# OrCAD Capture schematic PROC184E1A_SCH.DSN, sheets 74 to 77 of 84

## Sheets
74 78. EVM SOC CURRENT_SENSE_RES: size C; title: SOC Current Sense Resistors; note: PROC184_SCH
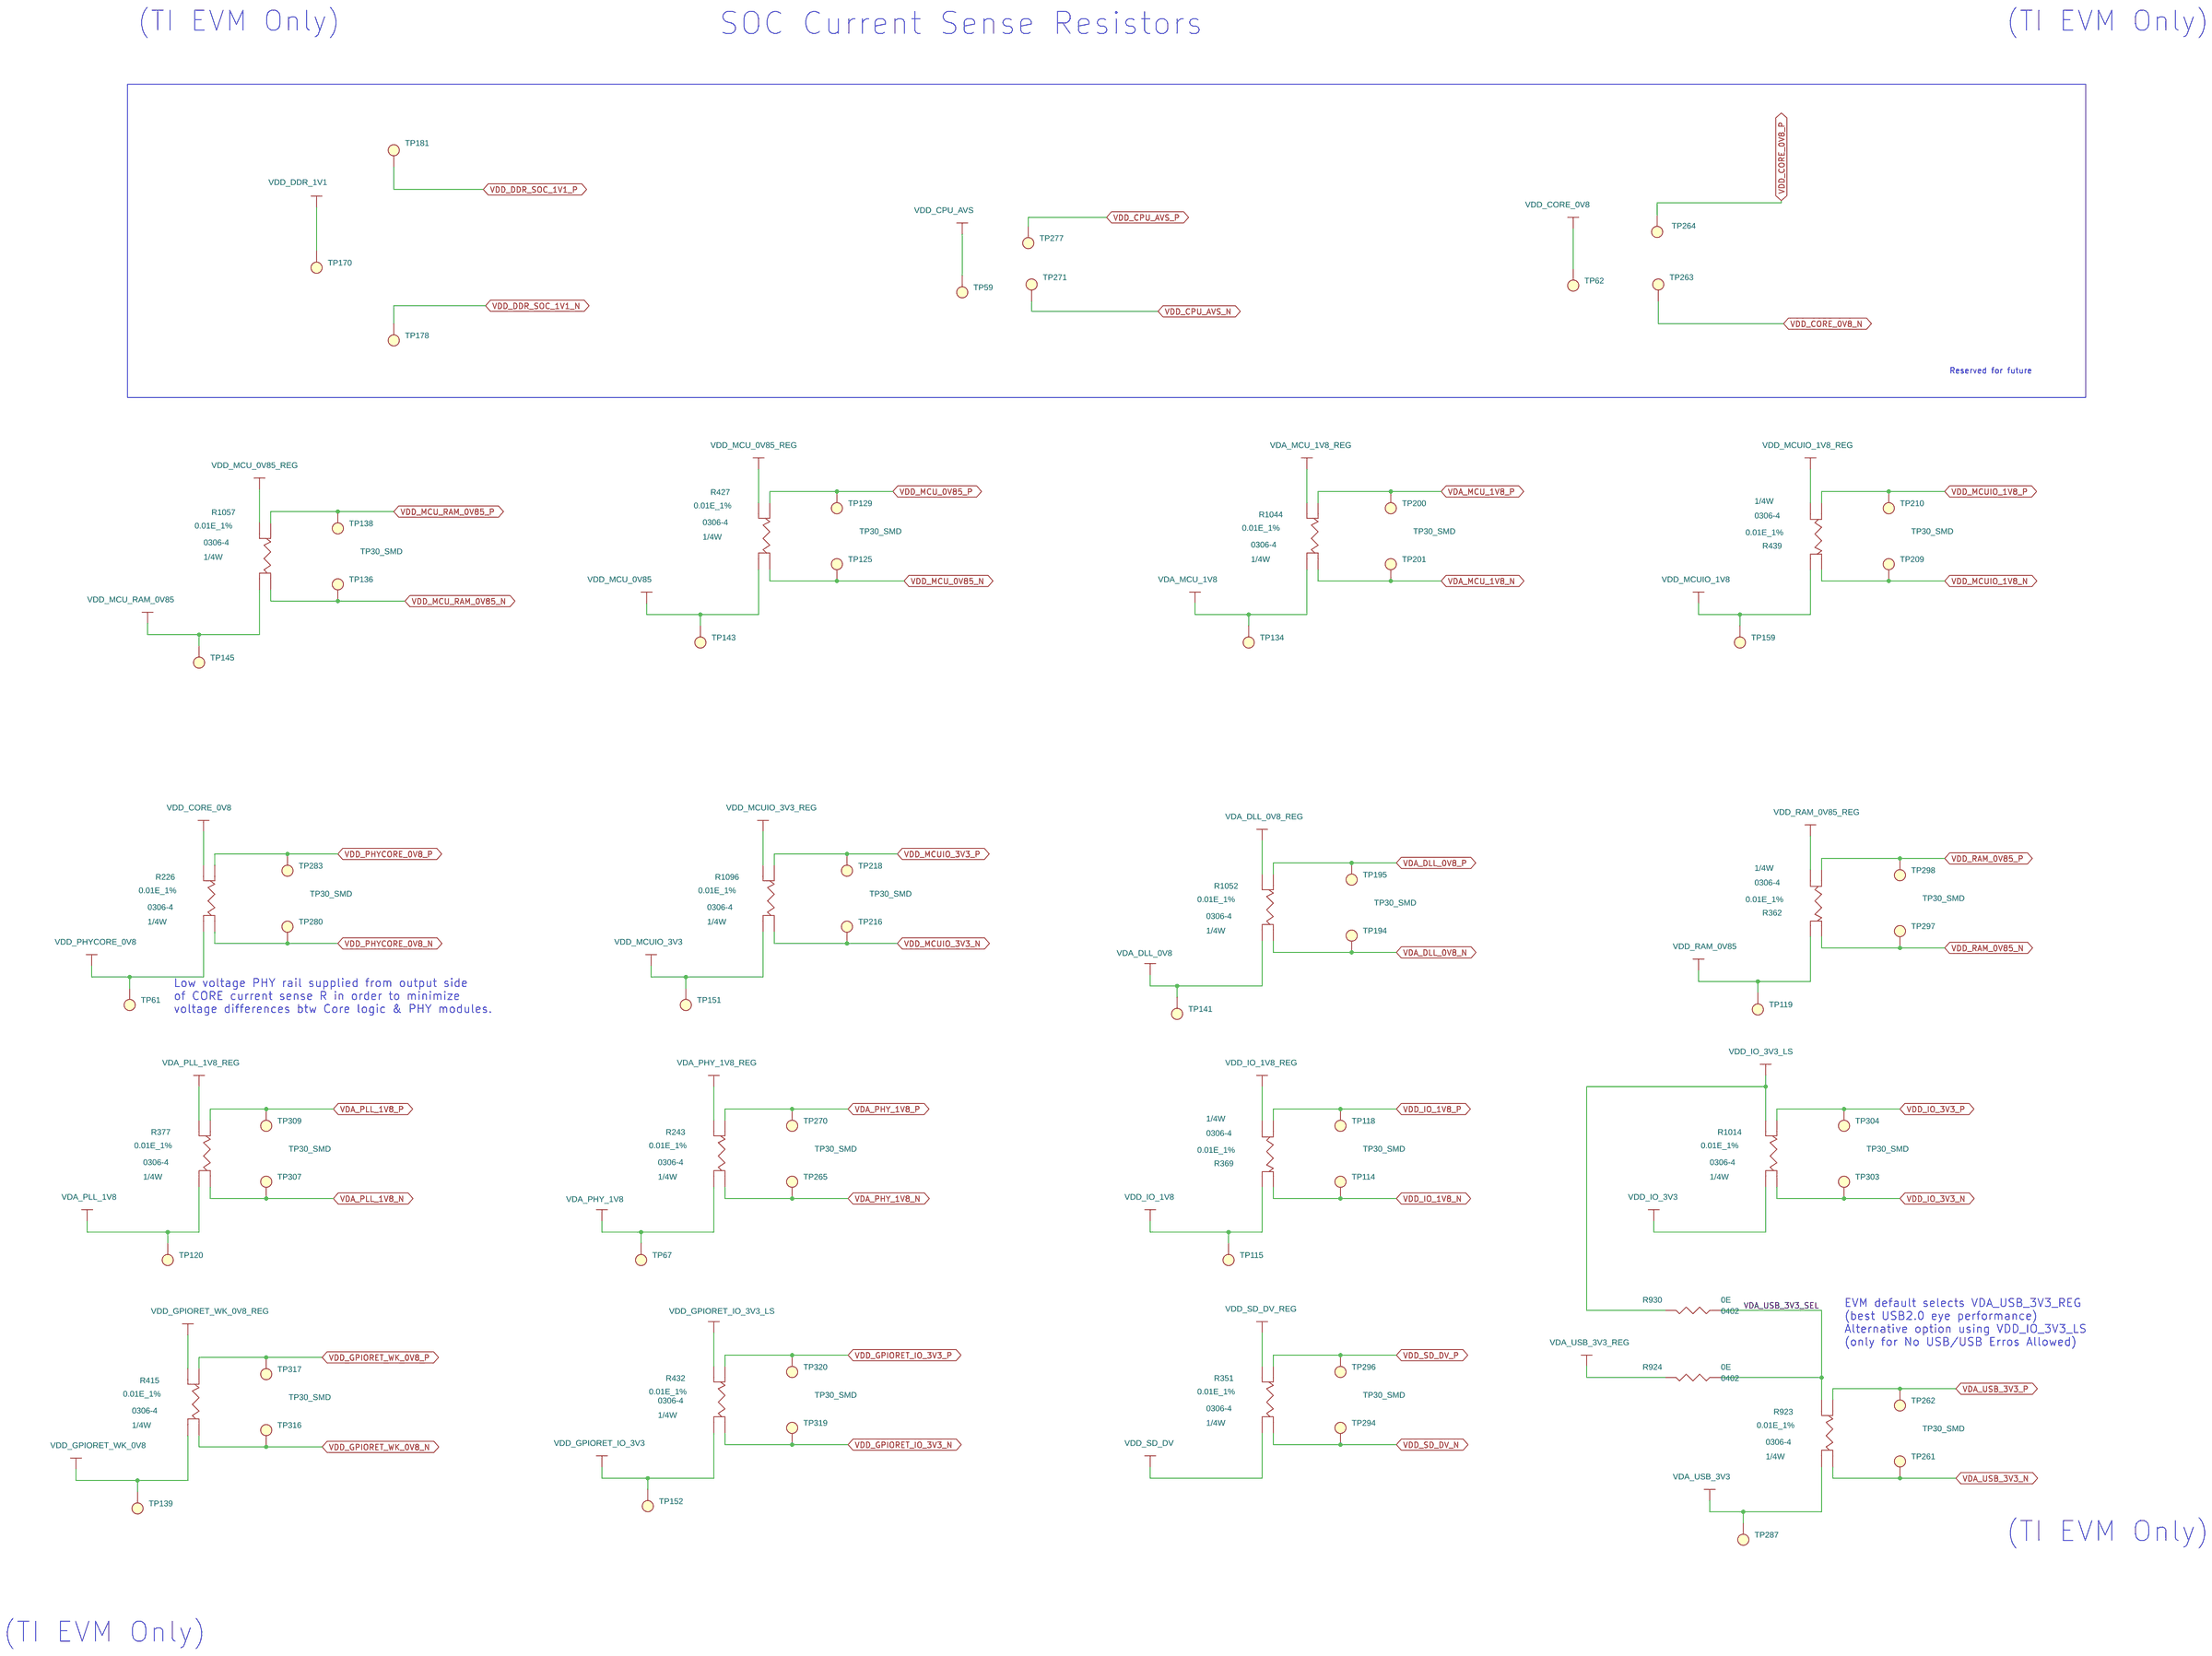
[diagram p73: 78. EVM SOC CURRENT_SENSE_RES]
75 79. EVM PERIP_CURRENT_SENSE_RES: size C; title: Peripheral Current Sense Resistors; note: PROC184_SCH
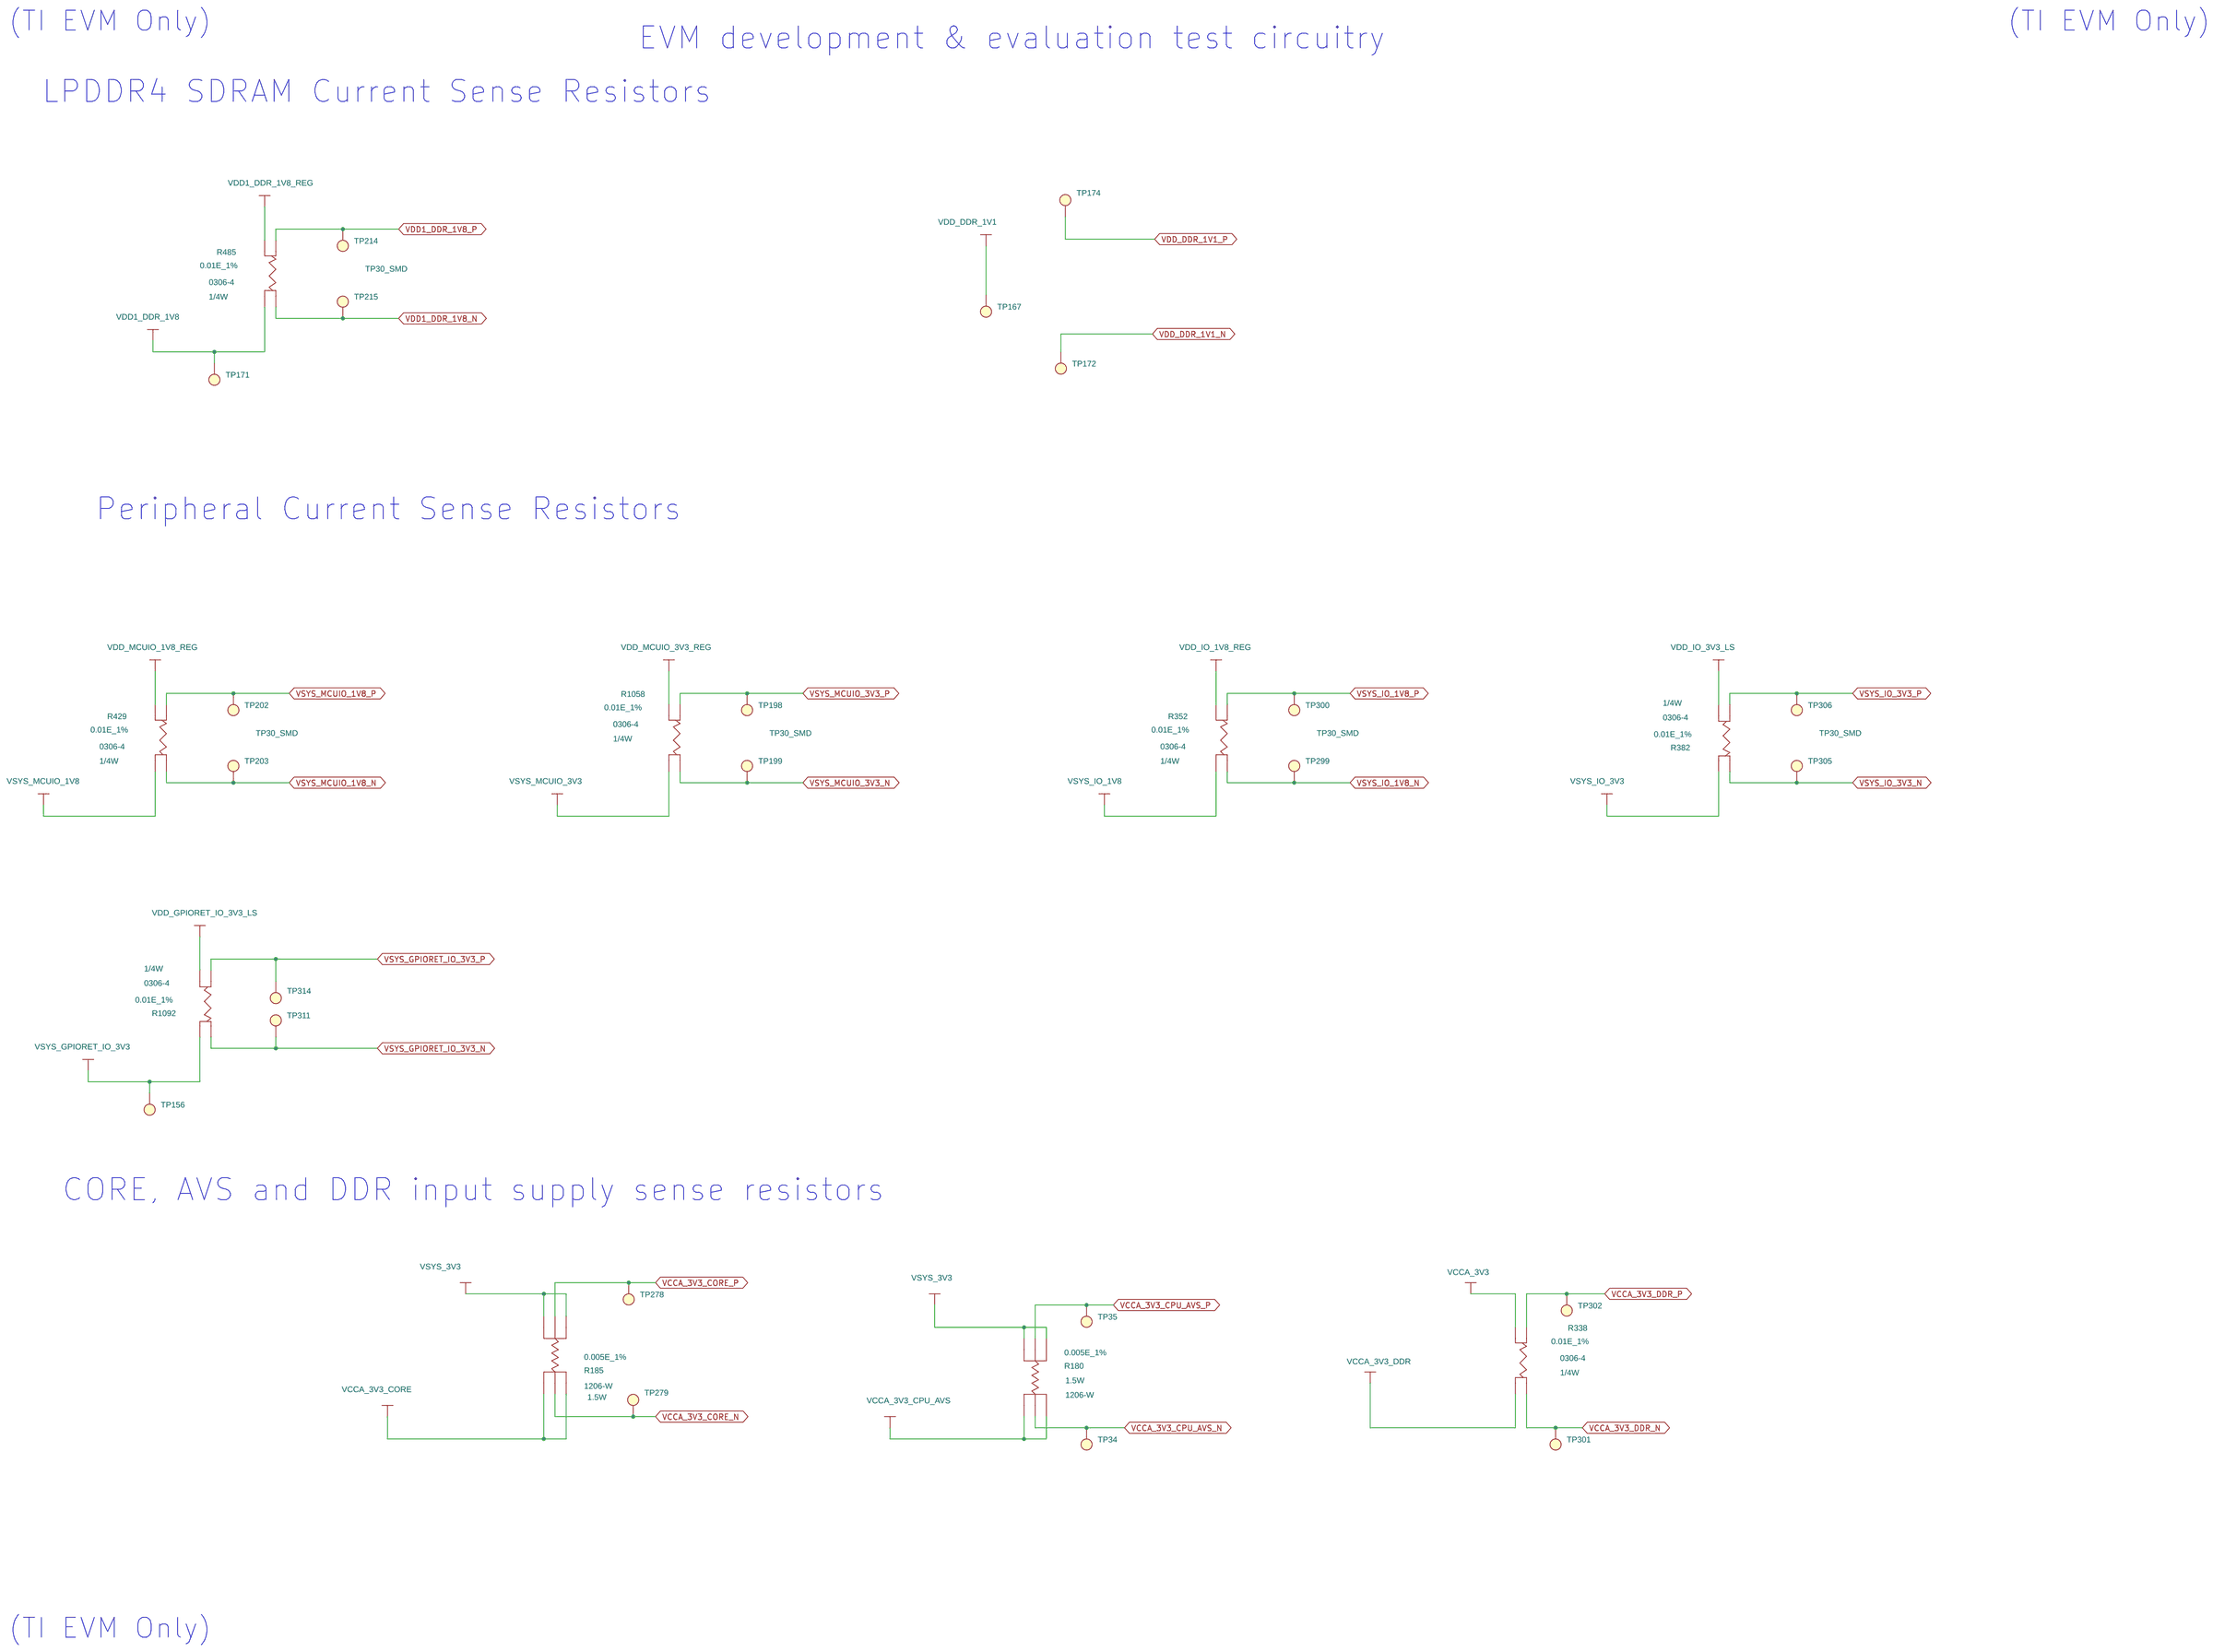
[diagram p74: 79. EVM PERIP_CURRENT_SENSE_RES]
76 80. CURRENT MONITORS #1: size C; title: CURRENT MONITORS #1; note: PROC184_SCH
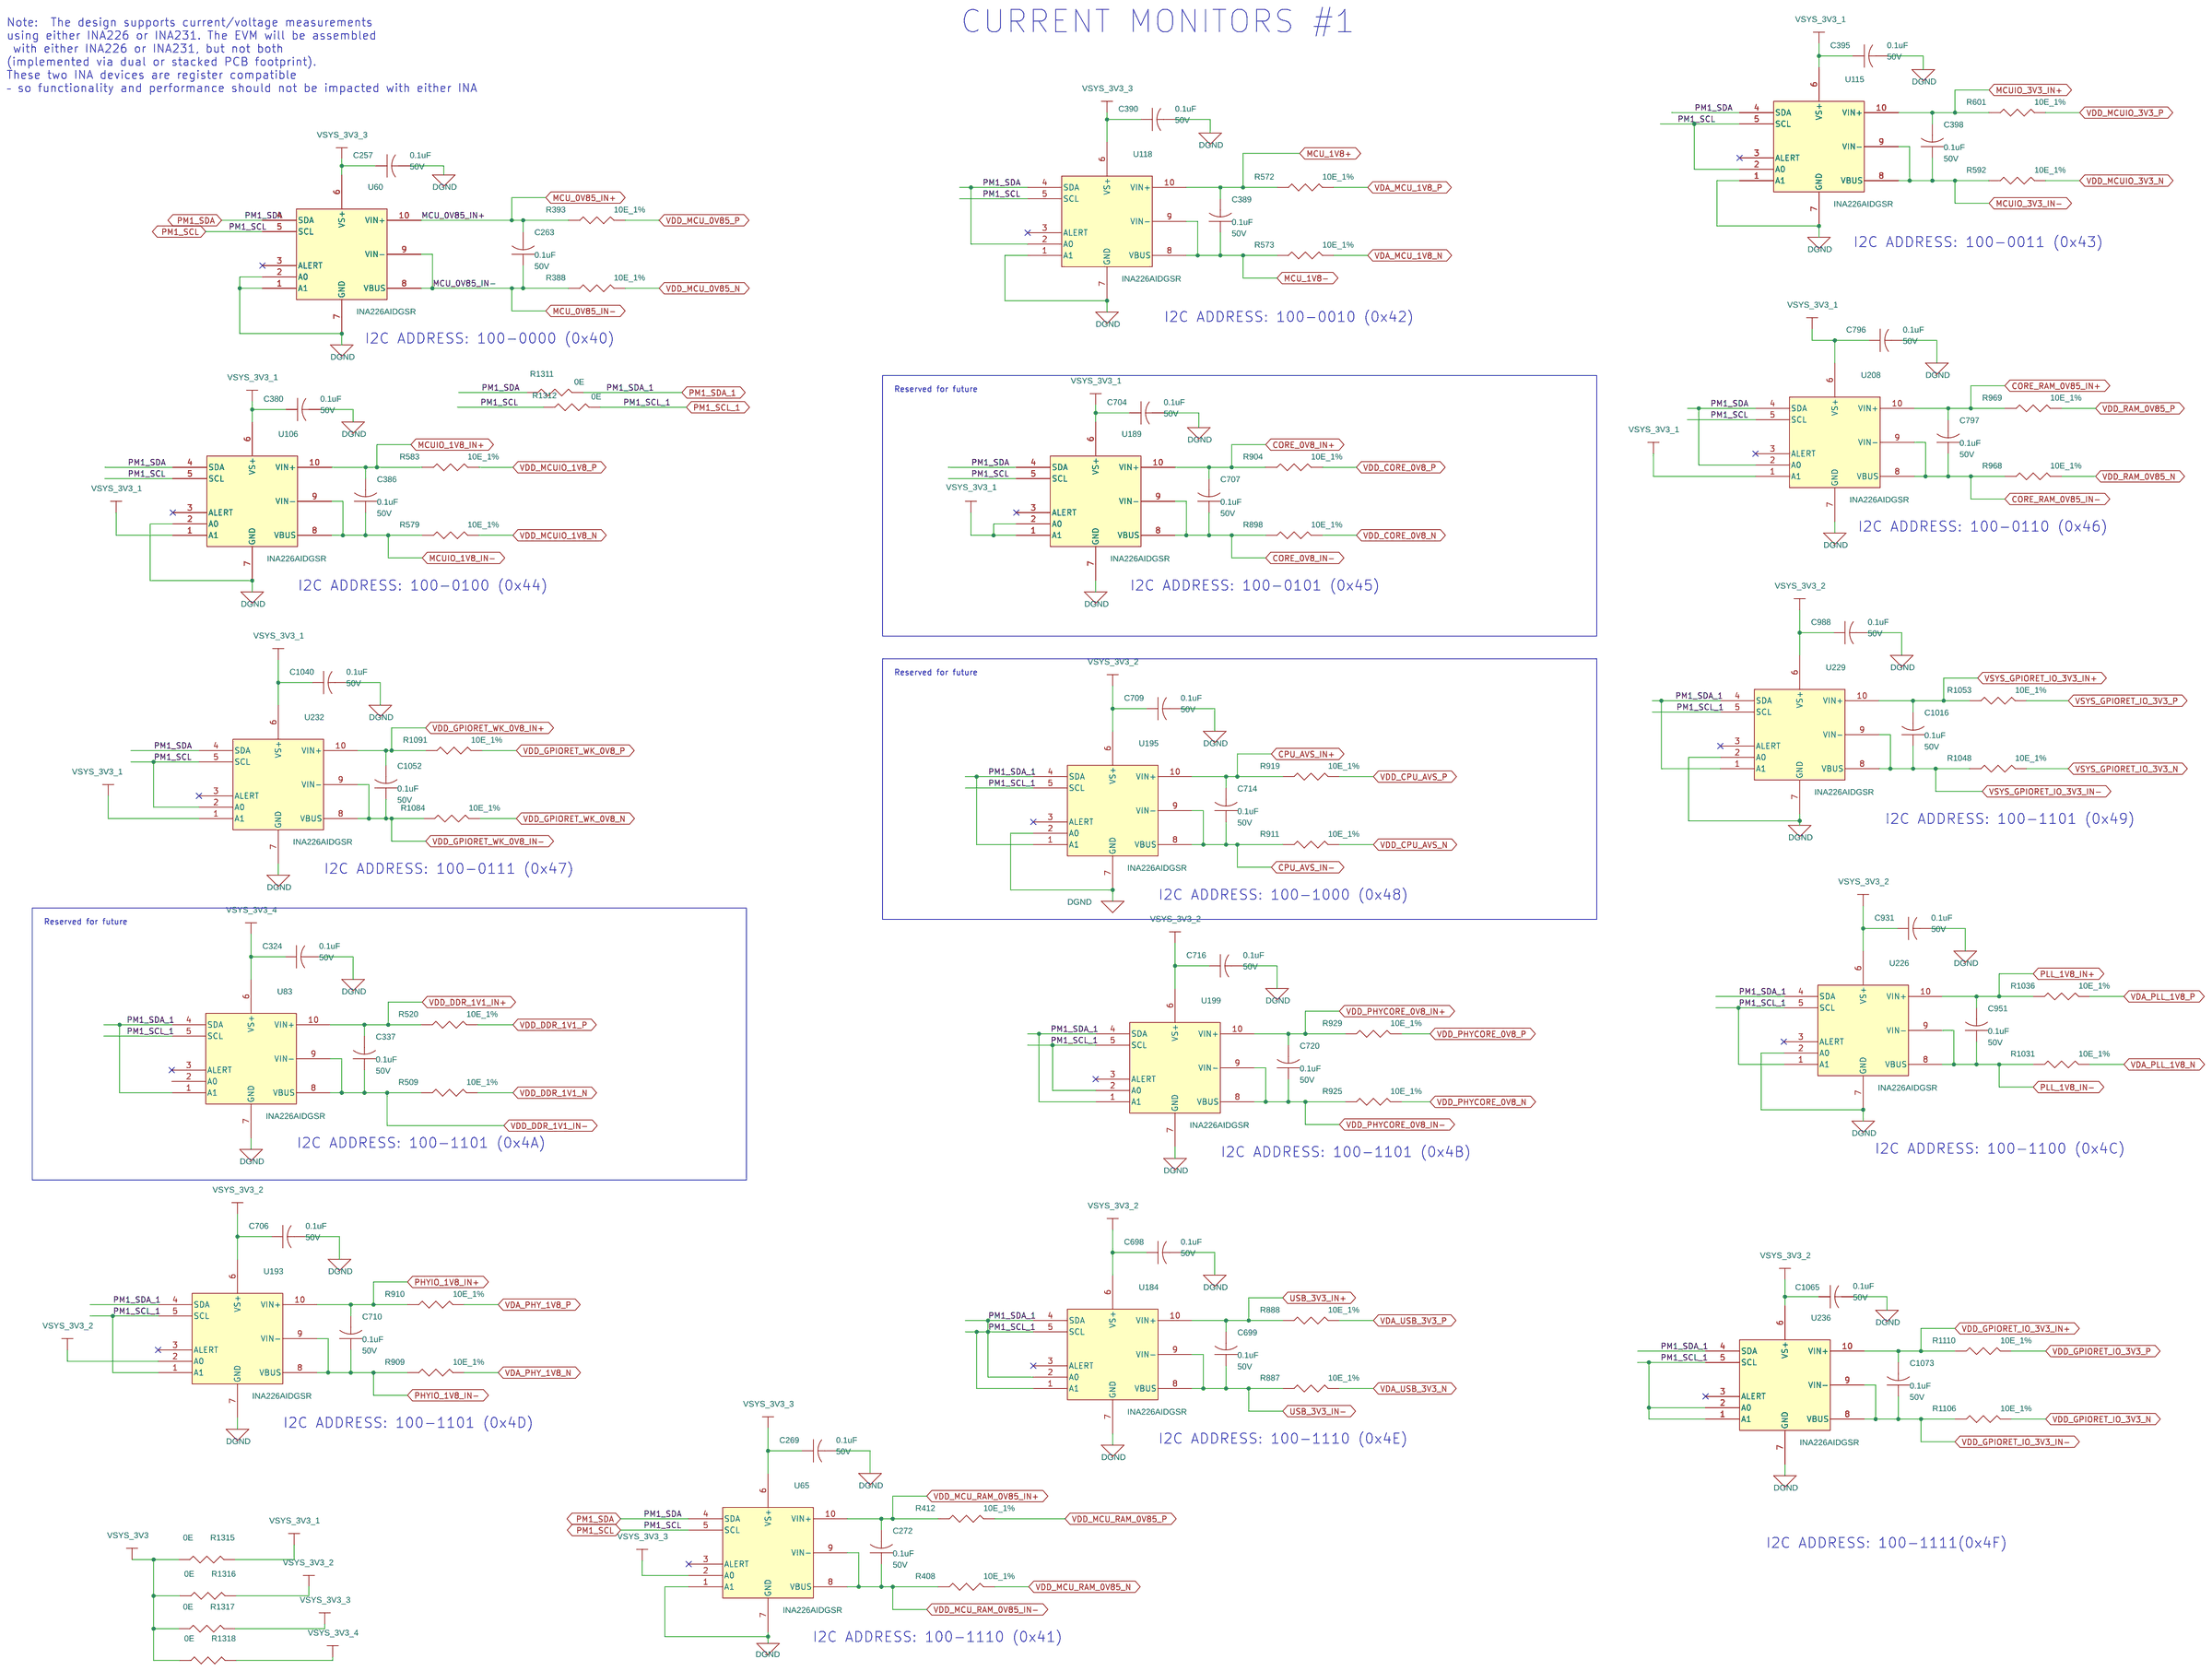
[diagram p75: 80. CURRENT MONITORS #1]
77 81. CURRENT MONITORS #2: size C; title: CURRENT MONITORS #2; note: PROC184_SCH

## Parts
sheet 78. EVM SOC CURRENT_SENSE_RES
R226  0.01E_1%  [RES_FC4L16_0306-4_0-7]
R243  0.01E_1%  [RES_FC4L16_0306-4_0-7]
R351  0.01E_1%  [RES_FC4L16_0306-4_0-7]
R362  0.01E_1%  [RES_FC4L16_0306-4_0-7]
R369  0.01E_1%  [RES_FC4L16_0306-4_0-7]
R377  0.01E_1%  [RES_FC4L16_0306-4_0-7]
R415  0.01E_1%  [RES_FC4L16_0306-4_0-7]
R427  0.01E_1%  [RES_FC4L16_0306-4_0-7]
R432  0.01E_1%  [RES_FC4L16_0306-4_0-7]
R439  0.01E_1%  [RES_FC4L16_0306-4_0-7]
R923  0.01E_1%  [RES_FC4L16_0306-4_0-7]
R924  0E  [RES0402_0-5]
R930  0E  [RES0402_0-5]
R1014  0.01E_1%  [RES_FC4L16_0306-4_0-7]
R1044  0.01E_1%  [RES_FC4L16_0306-4_0-7]
R1052  0.01E_1%  [RES_FC4L16_0306-4_0-7]
R1057  0.01E_1%  [RES_FC4L16_0306-4_0-7]
R1096  0.01E_1%  [RES_FC4L16_0306-4_0-7]
TP59  TP30_SMD  [TP30_SMD]
TP61  TP30_SMD  [TP30_SMD]
TP62  TP30_SMD  [TP30_SMD]
TP67  TP30_SMD  [TP30_SMD]
TP114  TP30_SMD  [TP30_SMD]
TP115  TP30_SMD  [TP30_SMD]
TP118  TP30_SMD  [TP30_SMD]
TP119  TP30_SMD  [TP30_SMD]
TP120  TP30_SMD  [TP30_SMD]
TP125  TP30_SMD  [TP30_SMD]
TP129  TP30_SMD  [TP30_SMD]
TP134  TP30_SMD  [TP30_SMD]
TP136  TP30_SMD  [TP30_SMD]
TP138  TP30_SMD  [TP30_SMD]
TP139  TP30_SMD  [TP30_SMD]
TP141  TP30_SMD  [TP30_SMD]
TP143  TP30_SMD  [TP30_SMD]
TP145  TP30_SMD  [TP30_SMD]
TP151  TP30_SMD  [TP30_SMD]
TP152  TP30_SMD  [TP30_SMD]
TP159  TP30_SMD  [TP30_SMD]
TP170  TP30_SMD  [TP30_SMD]
TP178  TP30_SMD  [TP30_SMD]
TP181  TP30_SMD  [TP30_SMD]
TP194  TP30_SMD  [TP30_SMD]
TP195  TP30_SMD  [TP30_SMD]
TP200  TP30_SMD  [TP30_SMD]
TP201  TP30_SMD  [TP30_SMD]
TP209  TP30_SMD  [TP30_SMD]
TP210  TP30_SMD  [TP30_SMD]
TP216  TP30_SMD  [TP30_SMD]
TP218  TP30_SMD  [TP30_SMD]
TP261  TP30_SMD  [TP30_SMD]
TP262  TP30_SMD  [TP30_SMD]
TP263  TP30_SMD  [TP30_SMD]
TP264  TP30_SMD  [TP30_SMD]
TP265  TP30_SMD  [TP30_SMD]
TP270  TP30_SMD  [TP30_SMD]
TP271  TP30_SMD  [TP30_SMD]
TP277  TP30_SMD  [TP30_SMD]
TP280  TP30_SMD  [TP30_SMD]
TP283  TP30_SMD  [TP30_SMD]
TP287  TP30_SMD  [TP30_SMD]
TP294  TP30_SMD  [TP30_SMD]
TP296  TP30_SMD  [TP30_SMD]
TP297  TP30_SMD  [TP30_SMD]
TP298  TP30_SMD  [TP30_SMD]
TP303  TP30_SMD  [TP30_SMD]
TP304  TP30_SMD  [TP30_SMD]
TP307  TP30_SMD  [TP30_SMD]
TP309  TP30_SMD  [TP30_SMD]
TP316  TP30_SMD  [TP30_SMD]
TP317  TP30_SMD  [TP30_SMD]
TP319  TP30_SMD  [TP30_SMD]
TP320  TP30_SMD  [TP30_SMD]
sheet 79. EVM PERIP_CURRENT_SENSE_RES
R180  0.005E_1%  [RES_KRL3216_1206-6_0-7_TI]
R185  0.005E_1%  [RES_KRL3216_1206-6_0-7_TI]
R338  0.01E_1%  [RES_FC4L16_0306-4_0-7]
R352  0.01E_1%  [RES_FC4L16_0306-4_0-7]
R382  0.01E_1%  [RES_FC4L16_0306-4_0-7]
R429  0.01E_1%  [RES_FC4L16_0306-4_0-7]
R485  0.01E_1%  [RES_FC4L16_0306-4_0-7]
R1058  0.01E_1%  [RES_FC4L16_0306-4_0-7]
R1092  0.01E_1%  [RES_FC4L16_0306-4_0-7]
TP34  TP30_SMD  [TP30_SMD]
TP35  TP30_SMD  [TP30_SMD]
TP156  TP30_SMD  [TP30_SMD]
TP167  TP30_SMD  [TP30_SMD]
TP171  TP30_SMD  [TP30_SMD]
TP172  TP30_SMD  [TP30_SMD]
TP174  TP30_SMD  [TP30_SMD]
TP198  TP30_SMD  [TP30_SMD]
TP199  TP30_SMD  [TP30_SMD]
TP202  TP30_SMD  [TP30_SMD]
TP203  TP30_SMD  [TP30_SMD]
TP214  TP30_SMD  [TP30_SMD]
TP215  TP30_SMD  [TP30_SMD]
TP278  TP30_SMD  [TP30_SMD]
TP279  TP30_SMD  [TP30_SMD]
TP299  TP30_SMD  [TP30_SMD]
TP300  TP30_SMD  [TP30_SMD]
TP301  TP30_SMD  [TP30_SMD]
TP302  TP30_SMD  [TP30_SMD]
TP305  TP30_SMD  [TP30_SMD]
TP306  TP30_SMD  [TP30_SMD]
TP311  TP30_SMD  [TP30_SMD]
TP314  TP30_SMD  [TP30_SMD]
sheet 80. CURRENT MONITORS #1
C257  0.1uF  [CAP0402_0-75]
C263  0.1uF  [CAP0402_0-75]
C269  0.1uF  [CAP0402_0-75]
C272  0.1uF  [CAP0402_0-75]
C324  0.1uF  [CAP0402_0-75]
C337  0.1uF  [CAP0402_0-75]
C380  0.1uF  [CAP0402_0-75]
C386  0.1uF  [CAP0402_0-75]
C389  0.1uF  [CAP0402_0-75]
C390  0.1uF  [CAP0402_0-75]
C395  0.1uF  [CAP0402_0-75]
C398  0.1uF  [CAP0402_0-75]
C698  0.1uF  [CAP0402_0-75]
C699  0.1uF  [CAP0402_0-75]
C704  0.1uF  [CAP0402_0-75]
C706  0.1uF  [CAP0402_0-75]
C707  0.1uF  [CAP0402_0-75]
C709  0.1uF  [CAP0402_0-75]
C710  0.1uF  [CAP0402_0-75]
C714  0.1uF  [CAP0402_0-75]
C716  0.1uF  [CAP0402_0-75]
C720  0.1uF  [CAP0402_0-75]
C796  0.1uF  [CAP0402_0-75]
C797  0.1uF  [CAP0402_0-75]
C931  0.1uF  [CAP0402_0-75]
C951  0.1uF  [CAP0402_0-75]
C988  0.1uF  [CAP0402_0-75]
C1016  0.1uF  [CAP0402_0-75]
C1040  0.1uF  [CAP0402_0-75]
C1052  0.1uF  [CAP0402_0-75]
C1065  0.1uF  [CAP0402_0-75]
C1073  0.1uF  [CAP0402_0-75]
R388  10E_1%  [RES0402_0-5]
R393  10E_1%  [RES0402_0-5]
R408  10E_1%  [RES0402_0-5]
R412  10E_1%  [RES0402_0-5]
R509  10E_1%  [RES0402_0-5]
R520  10E_1%  [RES0402_0-5]
R572  10E_1%  [RES0402_0-5]
R573  10E_1%  [RES0402_0-5]
R579  10E_1%  [RES0402_0-5]
R583  10E_1%  [RES0402_0-5]
R592  10E_1%  [RES0402_0-5]
R601  10E_1%  [RES0402_0-5]
R887  10E_1%  [RES0402_0-5]
R888  10E_1%  [RES0402_0-5]
R898  10E_1%  [RES0402_0-5]
R904  10E_1%  [RES0402_0-5]
R909  10E_1%  [RES0402_0-5]
R910  10E_1%  [RES0402_0-5]
R911  10E_1%  [RES0402_0-5]
R919  10E_1%  [RES0402_0-5]
R925  10E_1%  [RES0402_0-5]
R929  10E_1%  [RES0402_0-5]
R968  10E_1%  [RES0402_0-5]
R969  10E_1%  [RES0402_0-5]
R1031  10E_1%  [RES0402_0-5]
R1036  10E_1%  [RES0402_0-5]
R1048  10E_1%  [RES0402_0-5]
R1053  10E_1%  [RES0402_0-5]
R1084  10E_1%  [RES0402_0-5]
R1091  10E_1%  [RES0402_0-5]
R1106  10E_1%  [RES0402_0-5]
R1110  10E_1%  [RES0402_0-5]
R1311  0E  [RES0402_0-5]
R1312  0E  [RES0402_0-5]
R1315  0E  [RES0603_0-75]
R1316  0E  [RES0603_0-75]
R1317  0E  [RES0603_0-75]
R1318  0E  [RES0603_0-75]
U60  INA226AIDGSR  [MSOP10_19-68_120X120_1-1]
U65  INA226AIDGSR  [MSOP10_19-68_120X120_1-1]
U83  INA226AIDGSR  [MSOP10_19-68_120X120_1-1]
U106  INA226AIDGSR  [MSOP10_19-68_120X120_1-1]
U115  INA226AIDGSR  [MSOP10_19-68_120X120_1-1]
U118  INA226AIDGSR  [MSOP10_19-68_120X120_1-1]
U184  INA226AIDGSR  [MSOP10_19-68_120X120_1-1]
U189  INA226AIDGSR  [MSOP10_19-68_120X120_1-1]
U193  INA226AIDGSR  [MSOP10_19-68_120X120_1-1]
U195  INA226AIDGSR  [MSOP10_19-68_120X120_1-1]
U199  INA226AIDGSR  [MSOP10_19-68_120X120_1-1]
U208  INA226AIDGSR  [MSOP10_19-68_120X120_1-1]
U226  INA226AIDGSR  [MSOP10_19-68_120X120_1-1]
U229  INA226AIDGSR  [MSOP10_19-68_120X120_1-1]
U232  INA226AIDGSR  [MSOP10_19-68_120X120_1-1]
U236  INA226AIDGSR  [MSOP10_19-68_120X120_1-1]
sheet 81. CURRENT MONITORS #2
C145  0.1uF  [CAP0402_0-75]
C146  0.1uF  [CAP0402_0-75]
C250  0.1uF  [CAP0402_0-75]
C251  0.1uF  [CAP0402_0-75]
C348  0.1uF  [CAP0402_0-75]
C358  0.1uF  [CAP0402_0-75]
C366  0.1uF  [CAP0402_0-75]
C371  0.1uF  [CAP0402_0-75]
C387  0.1uF  [CAP0402_0-75]
C388  0.1uF  [CAP0402_0-75]
C391  0.1uF  [CAP0402_0-75]
C392  0.1uF  [CAP0402_0-75]
C402  0.1uF  [CAP0402_0-75]
C403  0.1uF  [CAP0402_0-75]
C586  0.1uF  [CAP0402_0-75]
C587  0.1uF  [CAP0402_0-75]
C722  0.1uF  [CAP0402_0-75]
C723  0.1uF  [CAP0402_0-75]
C798  0.1uF  [CAP0402_0-75]
C799  0.1uF  [CAP0402_0-75]
C800  0.1uF  [CAP0402_0-75]
C801  0.1uF  [CAP0402_0-75]
C805  0.1uF  [CAP0402_0-75]
C812  0.1uF  [CAP0402_0-75]
C823  0.1uF  [CAP0402_0-75]
C858  0.1uF  [CAP0402_0-75]
C882  0.1uF  [CAP0402_0-75]
C896  0.1uF  [CAP0402_0-75]
C919  0.1uF  [CAP0402_0-75]
C949  0.1uF  [CAP0402_0-75]
C1057  0.1uF  [CAP0402_0-75]
C1058  0.1uF  [CAP0402_0-75]
R178  10E_1%  [RES0402_0-5]
R179  10E_1%  [RES0402_0-5]
R359  10E_1%  [RES0402_0-5]
R370  10E_1%  [RES0402_0-5]
R551  10E_1%  [RES0402_0-5]
R555  10E_1%  [RES0402_0-5]
R558  10E_1%  [RES0402_0-5]
R562  10E_1%  [RES0402_0-5]
R570  10E_1%  [RES0402_0-5]
R571  10E_1%  [RES0402_0-5]
R574  10E_1%  [RES0402_0-5]
R575  10E_1%  [RES0402_0-5]
R594  10E_1%  [RES0402_0-5]
R595  10E_1%  [RES0402_0-5]
R800  10E_1%  [RES0402_0-5]
R801  10E_1%  [RES0402_0-5]
R927  10E_1%  [RES0402_0-5]
R928  10E_1%  [RES0402_0-5]
R971  10E_1%  [RES0402_0-5]
R972  10E_1%  [RES0402_0-5]
R973  10E_1%  [RES0402_0-5]
R974  10E_1%  [RES0402_0-5]
R975  10E_1%  [RES0402_0-5]
R977  10E_1%  [RES0402_0-5]
R983  10E_1%  [RES0402_0-5]
R991  10E_1%  [RES0402_0-5]
R1013  10E_1%  [RES0402_0-5]
R1015  10E_1%  [RES0402_0-5]
R1021  10E_1%  [RES0402_0-5]
R1024  10E_1%  [RES0402_0-5]
R1082  10E_1%  [RES0402_0-5]
R1083  10E_1%  [RES0402_0-5]
R1313  0E  [RES0402_0-5]
R1314  0E  [RES0402_0-5]
U32  INA226AIDGSR  [MSOP10_19-68_120X120_1-1]
U56  INA226AIDGSR  [MSOP10_19-68_120X120_1-1]
U94  INA226AIDGSR  [MSOP10_19-68_120X120_1-1]
U100  INA226AIDGSR  [MSOP10_19-68_120X120_1-1]
U117  INA226AIDGSR  [MSOP10_19-68_120X120_1-1]
U120  INA226AIDGSR  [MSOP10_19-68_120X120_1-1]
U128  INA226AIDGSR  [MSOP10_19-68_120X120_1-1]
U172  INA226AIDGSR  [MSOP10_19-68_120X120_1-1]
U203  INA226AIDGSR  [MSOP10_19-68_120X120_1-1]
U209  INA226AIDGSR  [MSOP10_19-68_120X120_1-1]
U212  INA226AIDGSR  [MSOP10_19-68_120X120_1-1]
U215  INA226AIDGSR  [MSOP10_19-68_120X120_1-1]
U218  INA226AIDGSR  [MSOP10_19-68_120X120_1-1]
U221  INA226AIDGSR  [MSOP10_19-68_120X120_1-1]
U224  INA226AIDGSR  [MSOP10_19-68_120X120_1-1]
U239  INA226AIDGSR  [MSOP10_19-68_120X120_1-1]

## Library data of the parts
R226 R243 R338 R351 R352 R362 R369 R377 R382 R415 R427 R429 R432 R439 R485 R923 R1014 R1044 R1052 R1057 R1058 R1092 R1096 = RESISTOR-4TERM: RES CURRENT SENSE 0.01E 1/4W 1% 0306-4; Chkd/date: MANIRAJA/261018; Crtd /date: ALVY/261018; Custom_Duty: 15%; Customs_HS_Code: 85332119; Distributor_name: DIGIKEY; Distributor_part_number: FC4L16R010FERCT-ND; Footprint Path: Y:\MIS_DATABASE\Library\ALTIUM_TOOL\PCB_FOOTPRINTS\Altium_Footprint_Lib.PcbLib; Height: 0.70MM; Library Path: Y:\MIS_DATABASE\Library\ALTIUM_TOOL\SCHEMATICS_PARTS\MS_DISCRETE_Library.schlib; Manufacturer: OHMITE; Mfr_name: OHMITE; Mfr_part_number: FC4L16R010FER; Mistral Part No: 110018100017-R; Package: 0306-4; Part_type: RESISTORS\FIXED; Project: TI_J7ES_EVM_SOM; RoHS: RoHS; Temperature: -40°C+125°C; Tolerance: 1%; Voltage: NA; Wattage: 1/4W; Weight: 4mg; Datasheet: Y:\MIS_DATABASE\DATASHEETS\RESISTORS\FC4L-SERIES.PDF
R924 R930 R1311-R1314 = RESISTOR: RES 0E 1/10W JUMPER 0402; Chkd/date: VASANTHA/061216; Crtd /date: NAVEED/201014; Custom_Duty: 15%; Customs_HS_Code: 85332119; Distributor_name: DIGIKEY; Distributor_part_number: P0.0JCT-ND; Footprint Path: Y:\MIS_DATABASE\Library\ALTIUM_TOOL\PCB_FOOTPRINTS\Altium_Footprint_Lib.PcbLib; Height: 0.40MM; IBISSP_MODLES: VALUE REPEATING 2 TIME; Library Path: Y:\MIS_DATABASE\Library\ALTIUM_TOOL\SCHEMATICS_PARTS\MS_DISCRETE_Library.schlib; Manufacturer: PANASONIC-ECG; Mfr_name: PANASONIC-ECG; Mfr_part_number: ERJ-2GE0R00X; Mistral Part No: 110018030052-R; Package: 0402; Part_type: RESISTORS\FIXED; Project: AEGIS POM; RoHS: RoHS; Temperature: -55°C+155°C; Tolerance: NA; Voltage: NA; Wattage: 1/10W; Weight: 0.8mg; Datasheet: Y:\MIS_DATABASE\DATASHEETS\RESISTORS\PAN-ERJSER_NOV17.PDF
TP34 TP35 TP59 TP61 TP62 TP67 TP114 TP115 TP118-TP120 TP125 TP129 TP134 TP136 TP138 TP139 TP141 TP143 TP145 TP151 TP152 TP156 TP159 TP167 TP170-TP172 TP174 TP178 TP181 TP194 TP195 TP198-TP203 TP209 TP210 TP214-TP216 TP218 TP261-TP265 TP270 TP271 TP277-TP280 TP283 TP287 TP294 TP296-TP307 TP309 TP311 TP314 TP316 TP317 TP319 TP320 = TESTPOINT: TESTPOINT CIR 30 SMD; Chkd/date: SHREESHAIL/171006; Crtd /date: MAZHAR/171006; Custom_Duty: NA; Customs_HS_Code: NA; Distributor_name: NA; Distributor_part_number: NA; Footprint Path: Y:\MIS_DATABASE\Library\ALTIUM_TOOL\PCB_FOOTPRINTS\Altium_Footprint_Lib.PcbLib; Height: NA; Library Path: Y:\MIS_DATABASE\Library\ALTIUM_TOOL\SCHEMATICS_PARTS\MS_DISCRETE_Library.schlib; MECHANICAL 3D STEP FILE: NA; Manufacturer: LOCAL; Mfr_name: LOCAL; Mistral Part No: 130009030930; Package: SMD; Project: BT MODULE_CSRBC04; RoHS: NA; Temperature: NA; Tolerance: NA; Voltage: NA; Wattage: NA; Weight: NA; Datasheet: NA
R180 R185 = RESISTOR_KRL_TI: RES 0.005E 1.5W 1% 1206-W; Chkd/date: MANIRAJA/020819; Crtd /date: ALVY/010819; Custom_Duty: 15%; Customs_HS_Code: 85332119; Distributor_name: MOUSER; Distributor_part_number: 754-KRL3216ECR005FT1; Footprint Path: Y:\MIS_DATABASE\Library\ALTIUM_TOOL\PCB_FOOTPRINTS\Altium_Footprint_Lib.PcbLib; Height: 0.70MM; Library Path: Y:\MIS_DATABASE\Library\ALTIUM_TOOL\SCHEMATICS_PARTS\MS_DISCRETE_Library.schlib; Mfr_name: SUSUMU; Mfr_part_number: KRL3216E-C-R005-F-T1_TI; Mistral Part No: 110019080004-R; Package: 1206-W; Part_type: RESISTORS\FIXED; Project: J7ES_SOM_DUAL-LEO_PMIC; RoHS: RoHS; Temperature: -55°C+175°C; Tolerance: 1%; Voltage: NA; Wattage: 1.5W; Weight: NA; Datasheet: Y:\MIS_DATABASE\DATASHEETS\RESISTORS\KRL_TI-SERIES.PDF
C145 C146 C250 C251 C257 C263 C269 C272 C324 C337 C348 C358 C366 C371 C380 C386-C392 C395 C398 C402 C403 C586 C587 C698 C699 C704 C706 C707 C709 C710 C714 C716 C720 C722 C723 C796-C801 C805 C812 C823 C858 C882 C896 C919 C931 C949 C951 C988 C1016 C1040 C1052 C1057 C1058 C1065 C1073 = CAP: CAP CERAMIC 0.1uF 50V 10% X7R 0402; Automotive Alternate_mfr_name: TDK; Automotive Alternate_mfr_part_number: CGA2B3X7R1H104K050BB; Chkd/date: MANIRAJA/261020; Crtd /date: ALVY/211020; Custom_Duty: 15%; Customs_HS_Code: 85322990; Direct Alternate_mfr_name: TDK; Direct Alternate_mfr_part_number: C1005X7R1H104K050BE; Distributor_name: DIGIKEY; Distributor_part_number: 490-10700-1-ND; Footprint Path: Y:\MIS_DATABASE\Library\ALTIUM_TOOL\PCB_FOOTPRINTS\Altium_Footprint_Lib.PcbLib; Height: 0.55MM; Library Path: Y:\MIS_DATABASE\Library\ALTIUM_TOOL\SCHEMATICS_PARTS\MS_DISCRETE_Library.schlib; Manufacturer: MURATA; Mfr_name: MURATA; Mfr_part_number: GRM155R71H104KE14D; Mistral Part No: 120011100014-R; Package: 0402; Part_type: CAPACITORS\CERAMIC; Project: J7_CP; RoHS: RoHS; Temperature: -55°C+125°C; Tolerance: 10%; Voltage: 50V; Wattage: NA; Weight: 3.1mg; Datasheet: Y:\MIS_DATABASE\DATASHEETS\CAPACITORS\GRM155R71H104KE14.PDF
R178 R179 R359 R370 R388 R393 R408 R412 R509 R520 R551 R555 R558 R562 R570-R575 R579 R583 R592 R594 R595 R601 R800 R801 R887 R888 R898 R904 R909-R911 R919 R925 R927-R929 R968 R969 R971-R975 R977 R983 R991 R1013 R1015 R1021 R1024 R1031 R1036 R1048 R1053 R1082-R1084 R1091 R1106 R1110 = RESISTOR: RES 10E 1/10W 1% 0402; Chkd/date: VASANTHA/201216; Crtd /date: MAZHAR/120505; Custom_Duty: 15%; Customs_HS_Code: 85332119; Distributor_name: DIGIKEY; Distributor_part_number: P10.0LCT-ND; Footprint Path: Y:\MIS_DATABASE\Library\ALTIUM_TOOL\PCB_FOOTPRINTS\Altium_Footprint_Lib.PcbLib; Height: 0.40MM; Library Path: Y:\MIS_DATABASE\Library\ALTIUM_TOOL\SCHEMATICS_PARTS\MS_DISCRETE_Library.schlib; Manufacturer: PANASONIC-ECG; Mfr_name: PANASONIC-ECG; Mfr_part_number: ERJ-2RKF10R0X; Mistral Part No: 110009030203-R; Package: 0402; Part_type: RESISTORS\FIXED; Project: CTP02_REVA_BASE; RoHS: RoHS; Temperature: -55°C+155°C; Tolerance: 1%; Voltage: NA; Wattage: 1/10W; Weight: 0.8mg; Datasheet: Y:\MIS_DATABASE\DATASHEETS\RESISTORS\PAN-ERJSER_NOV17.PDF
R1315-R1318 = RESISTOR: RES 0E 1/4W JUMPER 0603 (HP); Chkd/date: USMAN/170112; Crtd /date: CHAITHANYA/170112; Custom_Duty: 15%; Customs_HS_Code: 85332119; Distributor_name: DIGIKEY; Distributor_part_number: 541-0.0SBCT-ND; Footprint Path: Y:\MIS_DATABASE\Library\ALTIUM_TOOL\PCB_FOOTPRINTS\Altium_Footprint_Lib.PcbLib; Height: 0.55MM; Library Path: Y:\MIS_DATABASE\Library\ALTIUM_TOOL\SCHEMATICS_PARTS\MS_DISCRETE_Library.schlib; Manufacturer: VISHAY; Mfr_name: VISHAY; Mfr_part_number: CRCW06030000Z0EAHP; Mistral Part No: 110012010013-R; Package: 0603; Part_type: RESISTORS\FIXED; Project: NA10NG; Remarks: This part is pulse proof, high power; RoHS: RoHS; Temperature: -55°C+155°C; Tolerance: NA; Voltage: NA; Wattage: 1/4 W; Weight: 2mg; Datasheet: Y:\MIS_DATABASE\DATASHEETS\RESISTORS\CRCWXXX-HP_SEP16.PDF
U32 U56 U60 U65 U83 U94 U100 U106 U115 U117 U118 U120 U128 U172 U184 U189 U193 U195 U199 U203 U208 U209 U212 U215 U218 U221 U224 U226 U229 U232 U236 U239 = INA226AIDGS_MSOP10: IC BI-DIRECTIONAL CURRENT MONITER MSOP10; Automotive Alternate_mfr_name: TEXAS INSTRUMENTS; Automotive Alternate_mfr_part_number: INA226AQDGSRQ1; Chkd/date: MANIRAJA/050417; Crtd /date: MANIRAJA/050417; Custom_Duty: 15%; Customs_HS_Code: 85423100; Distributor_name: DIGIKEY; Distributor_part_number: 296-29034-1-ND; Footprint Path: Y:\MIS_DATABASE\Library\ALTIUM_TOOL\PCB_FOOTPRINTS\Altium_Footprint_Lib.PcbLib; Height: 1.10MM; Library Path: Y:\MIS_DATABASE\Library\ALTIUM_TOOL\SCHEMATICS_PARTS\MS_MISCINTERFACE_Library.schlib; Manufacturer: TEXAS INSTRUMENTS; Mfr_name: TEXAS INSTRUMENTS; Mistral Part No: 141011080019-R; Package: MSOP10; Part_type: ICS\INTERFACE; Project: DM385EVM_BASE-BOARD; RoHS: RoHS; Temperature: -40°C+125°C; Tolerance: NA; Voltage: NA; Wattage: NA; Weight: NA; Datasheet: Y:\MIS_DATABASE\DATASHEETS\ICS\INTERFACE\INA226.PDF

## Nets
DGND: C145.2 C250.2 C257.2 C269.2 C324.2 C348.2 C366.2 C380.2 C388.2 C390.2 C392.2 C395.2 C403.2 C586.2 C698.2 C704.2 C706.2 C709.2 C716.2 C723.2 C796.2 C798.2 C800.2 C805.2 C823.2 C882.2 C931.2 C949.2 C988.2 C1040.2 C1058.2 C1065.2 U32.7(GND) U56.1(A1) U56.2(A0) U56.7(GND) U60.1(A1) U60.2(A0) U60.7(GND) U65.1(A1) U65.7(GND) U83.7(GND) U94.2(A0) U94.7(GND) U100.7(GND) U106.2(A0) U106.7(GND) U115.1(A1) U115.7(GND) U117.7(GND) U118.1(A1) U118.7(GND) U120.7(GND) U128.1(A1) U128.7(GND) U172.2(A0) U172.7(GND) U184.7(GND) U189.7(GND) U193.7(GND) U195.2(A0) U195.7(GND) U199.7(GND) U203.7(GND) U208.7(GND) U209.2(A0) U209.7(GND) U212.7(GND) U215.1(A1) U215.7(GND) U218.1(A1) U218.7(GND) U221.7(GND) U224.7(GND) U226.2(A0) U226.7(GND) U229.2(A0) U229.7(GND) U232.7(GND) U236.7(GND) U239.7(GND) ; also on sheet 11 12 13 14 15 16 17 18 20 21 22 23 24 25 26 27 28 29 30 31 32 33 34 35 36 37 38 39 40 41 42 43 44 45 46 47 48 49 50 51 52 53 54 55 56 57 58 59 60 61 62 63 64 65 66 67 68 69 70 71 72 73 78 79 81 82 83 84
VCC_12V0_IN+: C1057.2 R1082.1 U239.10(VIN+) ; also on sheet 79
VCC_12V0_IN-: C1057.1 R1083.1 U239.8(VBUS) U239.9(VIN-) ; also on sheet 79
VCC_12V0_N: R1083.2 ; also on sheet 66
VCC_12V0_P: R1082.2 ; also on sheet 66
VCCA_3V3: R338.3 ; also on sheet 23 54 69 70 71 72 81
VCCA_3V3_CORE: R185.4 R185.6 ; also on sheet 71
VCCA_3V3_CORE_IN+: C722.2 R927.1 U203.10(VIN+) ; also on sheet 79
VCCA_3V3_CORE_IN-: C722.1 R928.1 U203.8(VBUS) U203.9(VIN-) ; also on sheet 79
VCCA_3V3_CORE_N: R185.5 R928.2 TP279.1(TP)
VCCA_3V3_CORE_P: R185.2 R927.2 TP278.1(TP)
VCCA_3V3_CPU_AVS: R180.4 R180.6 ; also on sheet 70
VCCA_3V3_CPU_AVS_IN+: C146.2 R179.1 U32.10(VIN+) ; also on sheet 79
VCCA_3V3_CPU_AVS_IN-: C146.1 R178.1 U32.8(VBUS) U32.9(VIN-) ; also on sheet 79
VCCA_3V3_CPU_AVS_N: R178.2 R180.5 TP34.1(TP)
VCCA_3V3_CPU_AVS_P: R179.2 R180.2 TP35.1(TP)
VCCA_3V3_DDR: R338.2 ; also on sheet 69
VCCA_3V3_DDR_IN+: C801.2 R974.1 U212.10(VIN+) ; also on sheet 79
VCCA_3V3_DDR_IN-: C801.1 R973.1 U212.8(VBUS) U212.9(VIN-) ; also on sheet 79
VCCA_3V3_DDR_N: R338.1 R973.2 TP301.1(TP)
VCCA_3V3_DDR_P: R338.4 R974.2 TP302.1(TP)
VDD1_DDR_1V8: R485.2 TP171.1(TP) ; also on sheet 14 15 54
VDD1_DDR_1V8_IN+: C402.2 R594.1 U128.10(VIN+) ; also on sheet 79
VDD1_DDR_1V8_IN-: C402.1 R595.1 U128.8(VBUS) U128.9(VIN-) ; also on sheet 79
VDD1_DDR_1V8_N: R485.1 R595.2 TP215.1(TP)
VDD1_DDR_1V8_P: R485.4 R594.2 TP214.1(TP)
VDD1_DDR_1V8_REG: R485.3 ; also on sheet 72
VDD_CORE_0V8: R226.3 TP62.1(TP) ; also on sheet 26 27 28 54 71
VDD_CORE_0V8_N: R898.2 TP263.1(TP)
VDD_CORE_0V8_P: R904.2 TP264.1(TP)
VDD_CPU_AVS: TP59.1(TP) ; also on sheet 22 27 28 54 70
VDD_CPU_AVS_N: R911.2 TP271.1(TP)
VDD_CPU_AVS_P: R919.2 TP277.1(TP)
VDD_DDR_1V1: TP167.1(TP) TP170.1(TP) ; also on sheet 14 15 26 28 69
VDD_DDR_1V1_IN+: C337.2 R520.1 U83.10(VIN+) ; also on sheet 78
VDD_DDR_1V1_IN-: C337.1 R509.1 U83.8(VBUS) U83.9(VIN-) ; also on sheet 78
VDD_DDR_1V1_N: R509.2 TP172.1(TP)
VDD_DDR_1V1_P: R520.2 TP174.1(TP)
VDD_DDR_SOC_1V1_IN+: C358.2 R555.1 U94.10(VIN+) ; also on sheet 79
VDD_DDR_SOC_1V1_IN-: C358.1 R551.1 U94.8(VBUS) U94.9(VIN-) ; also on sheet 79
VDD_DDR_SOC_1V1_N: R551.2 TP178.1(TP)
VDD_DDR_SOC_1V1_P: R555.2 TP181.1(TP)
VDD_GPIORET_IO_3V3: R432.2 TP152.1(TP) ; also on sheet 26 54 69
VDD_GPIORET_IO_3V3_IN+: C1073.2 R1110.1 U236.10(VIN+) ; also on sheet 78
VDD_GPIORET_IO_3V3_IN-: C1073.1 R1106.1 U236.8(VBUS) U236.9(VIN-) ; also on sheet 78
VDD_GPIORET_IO_3V3_LS: R432.3 R1092.2 ; also on sheet 72
VDD_GPIORET_IO_3V3_N: R432.1 R1106.2 TP319.1(TP)
VDD_GPIORET_IO_3V3_P: R432.4 R1110.2 TP320.1(TP)
VDD_GPIORET_WK_0V8: R415.2 TP139.1(TP) ; also on sheet 26 54
VDD_GPIORET_WK_0V8_IN+: C1052.2 R1091.1 U232.10(VIN+) ; also on sheet 78
VDD_GPIORET_WK_0V8_IN-: C1052.1 R1084.1 U232.8(VBUS) U232.9(VIN-) ; also on sheet 78
VDD_GPIORET_WK_0V8_N: R415.1 R1084.2 TP316.1(TP)
VDD_GPIORET_WK_0V8_P: R415.4 R1091.2 TP317.1(TP)
VDD_GPIORET_WK_0V8_REG: R415.3 ; also on sheet 72
VDD_IO_1V8: R369.3 TP115.1(TP) ; also on sheet 26 69 72
VDD_IO_1V8_IN+: C251.2 R370.1 U56.10(VIN+) ; also on sheet 79
VDD_IO_1V8_IN-: C251.1 R359.1 U56.8(VBUS) U56.9(VIN-) ; also on sheet 79
VDD_IO_1V8_N: R359.2 R369.4 TP114.1(TP)
VDD_IO_1V8_P: R369.1 R370.2 TP118.1(TP)
VDD_IO_1V8_REG: R352.3 R369.2 ; also on sheet 69
VDD_IO_3V3: R1014.2 ; also on sheet 26 54 72
VDD_IO_3V3_IN+: C858.2 R991.1 U218.10(VIN+) ; also on sheet 79
VDD_IO_3V3_IN-: C858.1 R983.1 U218.8(VBUS) U218.9(VIN-) ; also on sheet 79
VDD_IO_3V3_LS: R382.2 R930.2 R1014.3 ; also on sheet 72
VDD_IO_3V3_N: R983.2 R1014.1 TP303.1(TP)
VDD_IO_3V3_P: R991.2 R1014.4 TP304.1(TP)
VDD_MCU_0V85: R427.2 TP143.1(TP) ; also on sheet 26 27 28 54 69 72
VDD_MCU_0V85_N: R388.2 R427.1 TP125.1(TP)
VDD_MCU_0V85_P: R393.2 R427.4 TP129.1(TP)
VDD_MCU_0V85_REG: R427.3 R1057.3 ; also on sheet 69
VDD_MCU_RAM_0V85: R1057.2 TP145.1(TP) ; also on sheet 27
VDD_MCU_RAM_0V85_IN+: C272.2 R412.1 U65.10(VIN+) ; also on sheet 78
VDD_MCU_RAM_0V85_IN-: C272.1 R408.1 U65.8(VBUS) U65.9(VIN-) ; also on sheet 78
VDD_MCU_RAM_0V85_N: R408.2 R1057.1 TP136.1(TP)
VDD_MCU_RAM_0V85_P: R412.2 R1057.4 TP138.1(TP)
VDD_MCUIO_1V8: R439.3 TP159.1(TP) ; also on sheet 26 54 69
VDD_MCUIO_1V8_N: R439.4 R579.2 TP209.1(TP)
VDD_MCUIO_1V8_P: R439.1 R583.2 TP210.1(TP)
VDD_MCUIO_1V8_REG: R429.3 R439.2 ; also on sheet 69
VDD_MCUIO_3V3: R1096.2 TP151.1(TP) ; also on sheet 26 54 72
VDD_MCUIO_3V3_N: R592.2 R1096.1 TP216.1(TP)
VDD_MCUIO_3V3_P: R601.2 R1096.4 TP218.1(TP)
VDD_MCUIO_3V3_REG: R1058.3 R1096.3 ; also on sheet 69
VDD_PHYCORE_0V8: R226.2 TP61.1(TP) ; also on sheet 25
VDD_PHYCORE_0V8_IN+: C720.2 R929.1 U199.10(VIN+) ; also on sheet 78
VDD_PHYCORE_0V8_IN-: C720.1 R925.1 U199.8(VBUS) U199.9(VIN-) ; also on sheet 78
VDD_PHYCORE_0V8_N: R226.1 R925.2 TP280.1(TP)
VDD_PHYCORE_0V8_P: R226.4 R929.2 TP283.1(TP)
VDD_RAM_0V85: R362.3 TP119.1(TP) ; also on sheet 27 69
VDD_RAM_0V85_N: R362.4 R968.2 TP297.1(TP)
VDD_RAM_0V85_P: R362.1 R969.2 TP298.1(TP)
VDD_RAM_0V85_REG: R362.2 ; also on sheet 69
VDD_SD_DV: R351.2 ; also on sheet 26 40
VDD_SD_DV_IN+: C812.2 R977.1 U215.10(VIN+) ; also on sheet 79
VDD_SD_DV_IN-: C812.1 R975.1 U215.8(VBUS) U215.9(VIN-) ; also on sheet 79
VDD_SD_DV_N: R351.1 R975.2 TP294.1(TP)
VDD_SD_DV_P: R351.4 R977.2 TP296.1(TP)
VDD_SD_DV_REG: R351.3 ; also on sheet 72
CORE_0V8_IN+: C707.2 R904.1 U189.10(VIN+) ; also on sheet 78
CORE_0V8_IN-: C707.1 R898.1 U189.8(VBUS) U189.9(VIN-) ; also on sheet 78
CORE_RAM_0V85_IN+: C797.2 R969.1 U208.10(VIN+) ; also on sheet 78
CORE_RAM_0V85_IN-: C797.1 R968.1 U208.8(VBUS) U208.9(VIN-) ; also on sheet 78
CPU_AVS_IN+: C714.2 R919.1 U195.10(VIN+) ; also on sheet 78
CPU_AVS_IN-: C714.1 R911.1 U195.8(VBUS) U195.9(VIN-) ; also on sheet 78
DLL_0V8_IN+: C371.2 R562.1 U100.10(VIN+) ; also on sheet 79
DLL_0V8_IN-: C371.1 R558.1 U100.8(VBUS) U100.9(VIN-) ; also on sheet 79
MCU_0V85_IN+: C263.2 R393.1 U60.10(VIN+) ; also on sheet 78
MCU_0V85_IN-: C263.1 R388.1 U60.8(VBUS) U60.9(VIN-) ; also on sheet 78
MCU_1V8+: C389.2 R572.1 U118.10(VIN+) ; also on sheet 78
MCU_1V8-: C389.1 R573.1 U118.8(VBUS) U118.9(VIN-) ; also on sheet 78
MCUIO_1V8_IN+: C386.2 R583.1 U106.10(VIN+) ; also on sheet 78
MCUIO_1V8_IN-: C386.1 R579.1 U106.8(VBUS) U106.9(VIN-) ; also on sheet 78
MCUIO_3V3_IN+: C398.2 R601.1 U115.10(VIN+) ; also on sheet 78
MCUIO_3V3_IN-: C398.1 R592.1 U115.8(VBUS) U115.9(VIN-) ; also on sheet 78
PHYIO_1V8_IN+: C710.2 R910.1 U193.10(VIN+) ; also on sheet 78
PHYIO_1V8_IN-: C710.1 R909.1 U193.8(VBUS) U193.9(VIN-) ; also on sheet 78
PLL_1V8_IN+: C951.2 R1036.1 U226.10(VIN+) ; also on sheet 78
PLL_1V8_IN-: C951.1 R1031.1 U226.8(VBUS) U226.9(VIN-) ; also on sheet 78
PM1_SCL: R1312.1 U60.5(SCL) U65.5(SCL) U106.5(SCL) U115.2(A0) U115.5(SCL) U118.5(SCL) U189.5(SCL) U208.5(SCL) U232.2(A0) U232.5(SCL) ; also on sheet 47 63 73 78
PM1_SCL_1: R1312.2 U83.5(SCL) U184.1(A1) U184.5(SCL) U193.1(A1) U193.5(SCL) U195.5(SCL) U199.2(A0) U199.5(SCL) U226.1(A1) U226.5(SCL) U229.5(SCL) U236.1(A1) U236.2(A0) U236.5(SCL) ; also on sheet 78
PM1_SDA: R1311.1 U60.4(SDA) U65.4(SDA) U106.4(SDA) U115.4(SDA) U118.2(A0) U118.4(SDA) U189.4(SDA) U208.2(A0) U208.4(SDA) U232.4(SDA) ; also on sheet 47 63 73 78
PM1_SDA_1: R1311.2 U83.1(A1) U83.4(SDA) U184.2(A0) U184.4(SDA) U193.4(SDA) U195.1(A1) U195.4(SDA) U199.1(A1) U199.4(SDA) U226.4(SDA) U229.1(A1) U229.4(SDA) U236.4(SDA) ; also on sheet 78
PM2_SCL: R1314.1 U56.5(SCL) U94.5(SCL) U117.2(A0) U117.5(SCL) U120.5(SCL) U128.2(A0) U128.5(SCL) U203.5(SCL) U215.5(SCL) U218.5(SCL) ; also on sheet 47 62 63 73 79
PM2_SCL_1: R1314.2 U32.1(A1) U32.2(A0) U32.5(SCL) U100.1(A1) U100.5(SCL) U172.1(A1) U172.5(SCL) U209.5(SCL) U212.1(A1) U212.5(SCL) U221.5(SCL) U224.2(A0) U224.5(SCL) U239.5(SCL) ; also on sheet 79
PM2_SDA: R1313.1 U56.4(SDA) U94.4(SDA) U117.4(SDA) U120.2(A0) U120.4(SDA) U128.4(SDA) U203.4(SDA) U215.2(A0) U215.4(SDA) U218.4(SDA) ; also on sheet 47 62 63 73 79
PM2_SDA_1: R1313.2 U32.4(SDA) U100.2(A0) U100.4(SDA) U172.4(SDA) U209.1(A1) U209.4(SDA) U212.4(SDA) U221.1(A1) U221.4(SDA) U224.1(A1) U224.4(SDA) U239.1(A1) U239.2(A0) U239.4(SDA) ; also on sheet 79
USB_3V3_IN+: C699.2 R888.1 U184.10(VIN+) ; also on sheet 78
USB_3V3_IN-: C699.1 R887.1 U184.8(VBUS) U184.9(VIN-) ; also on sheet 78
VDA_DLL_0V8: R1052.2 TP141.1(TP) ; also on sheet 25 70
VDA_DLL_0V8_N: R558.2 R1052.1 TP194.1(TP)
VDA_DLL_0V8_P: R562.2 R1052.4 TP195.1(TP)
VDA_DLL_0V8_REG: R1052.3 ; also on sheet 69
VDA_MCU_1V8: R1044.2 TP134.1(TP) ; also on sheet 21 25 36 69
VDA_MCU_1V8_N: R573.2 R1044.1 TP201.1(TP)
VDA_MCU_1V8_P: R572.2 R1044.4 TP200.1(TP)
VDA_MCU_1V8_REG: R1044.3 ; also on sheet 18 69
VDA_PHY_1V8: R243.2 TP67.1(TP) ; also on sheet 25 54
VDA_PHY_1V8_N: R243.1 R909.2 TP265.1(TP)
VDA_PHY_1V8_P: R243.4 R910.2 TP270.1(TP)
VDA_PHY_1V8_REG: R243.3 ; also on sheet 72
VDA_PLL_1V8: R377.2 TP120.1(TP) ; also on sheet 25 54
VDA_PLL_1V8_N: R377.1 R1031.2 TP307.1(TP)
VDA_PLL_1V8_P: R377.4 R1036.2 TP309.1(TP)
VDA_PLL_1V8_REG: R377.3 ; also on sheet 72
VDA_USB_3V3: R923.2 TP287.1(TP) ; also on sheet 25
VDA_USB_3V3_N: R887.2 R923.1 TP261.1(TP)
VDA_USB_3V3_P: R888.2 R923.4 TP262.1(TP)
VDA_USB_3V3_REG: R924.2 ; also on sheet 72
VDA_USB_3V3_SEL: R923.3 R924.1 R930.1
VSYS_3V3: R180.1 R180.3 R185.1 R185.3 R1315.2 R1316.2 R1317.2 R1318.2 U221.2(A0) ; also on sheet 22 23 35 36 40 47 49 62 63 65 66 67 68 69 73 78 79
VSYS_3V3_1: C380.1 C395.1 C704.1 C723.1 C796.1 C805.1 C823.1 C1040.1 R1315.1 U106.1(A1) U106.6(VS+) U115.6(VS+) U189.1(A1) U189.2(A0) U189.6(VS+) U203.1(A1) U203.2(A0) U203.6(VS+) U208.1(A1) U208.6(VS+) U215.6(VS+) U218.2(A0) U218.6(VS+) U232.1(A1) U232.6(VS+) ; also on sheet 78 79
VSYS_3V3_2: C698.1 C706.1 C709.1 C716.1 C882.1 C931.1 C988.1 C1065.1 R1316.1 U184.6(VS+) U193.2(A0) U193.6(VS+) U195.6(VS+) U199.6(VS+) U221.6(VS+) U226.6(VS+) U229.6(VS+) U236.6(VS+) ; also on sheet 78 79
VSYS_3V3_3: C250.1 C257.1 C269.1 C348.1 C388.1 C390.1 C392.1 C403.1 R1317.1 U56.6(VS+) U60.6(VS+) U65.2(A0) U65.6(VS+) U94.1(A1) U94.6(VS+) U117.1(A1) U117.6(VS+) U118.6(VS+) U120.1(A1) U120.6(VS+) U128.6(VS+) ; also on sheet 78 79
VSYS_3V3_4: C145.1 C324.1 C366.1 C586.1 C798.1 C800.1 C949.1 C1058.1 R1318.1 U32.6(VS+) U83.6(VS+) U100.6(VS+) U172.6(VS+) U209.6(VS+) U212.2(A0) U212.6(VS+) U224.6(VS+) U239.6(VS+) ; also on sheet 78 79
VSYS_3V3_IN+: C587.2 R801.1 U172.10(VIN+) ; also on sheet 79
VSYS_3V3_IN-: C587.1 R800.1 U172.8(VBUS) U172.9(VIN-) ; also on sheet 79
VSYS_3V3_N: R800.2 ; also on sheet 67
VSYS_3V3_P: R801.2 ; also on sheet 67
VSYS_5V0_IN+: C919.2 R1021.1 U224.10(VIN+) ; also on sheet 79
VSYS_5V0_IN-: C919.1 R1024.1 U224.8(VBUS) U224.9(VIN-) ; also on sheet 79
VSYS_5V0_N: R1024.2 ; also on sheet 65
VSYS_5V0_P: R1021.2 ; also on sheet 65
VSYS_GPIORET_IO_3V3: R1092.3 TP156.1(TP) ; also on sheet 18
VSYS_GPIORET_IO_3V3_IN+: C1016.2 R1053.1 U229.10(VIN+) ; also on sheet 78
VSYS_GPIORET_IO_3V3_IN-: C1016.1 R1048.1 U229.8(VBUS) U229.9(VIN-) ; also on sheet 78
VSYS_GPIORET_IO_3V3_N: R1048.2 R1092.4 TP311.1(TP)
VSYS_GPIORET_IO_3V3_P: R1053.2 R1092.1 TP314.1(TP)
VSYS_IO_1V8: R352.2 ; also on sheet 30 32 33 34 37 38 41 42 61 65
VSYS_IO_1V8_IN+: C799.2 R972.1 U209.10(VIN+) ; also on sheet 79
VSYS_IO_1V8_IN-: C799.1 R971.1 U209.8(VBUS) U209.9(VIN-) ; also on sheet 79
VSYS_IO_1V8_N: R352.1 R971.2 TP299.1(TP)
VSYS_IO_1V8_P: R352.4 R972.2 TP300.1(TP)
VSYS_IO_3V3: R382.3 ; also on sheet 18 20 22 24 29 30 31 32 33 35 36 37 38 40 41 42 43 45 46 48 50 51 53 56 57 58 59 60 61 65 66 68 81 82
VSYS_IO_3V3_IN+: C896.2 R1015.1 U221.10(VIN+) ; also on sheet 79
VSYS_IO_3V3_IN-: C896.1 R1013.1 U221.8(VBUS) U221.9(VIN-) ; also on sheet 79
VSYS_IO_3V3_N: R382.4 R1013.2 TP305.1(TP)
VSYS_IO_3V3_P: R382.1 R1015.2 TP306.1(TP)
VSYS_MCUIO_1V8: R429.2 ; also on sheet 17 21 37 39 53 62 65
VSYS_MCUIO_1V8_IN+: C391.2 R574.1 U120.10(VIN+) ; also on sheet 79
VSYS_MCUIO_1V8_IN-: C391.1 R575.1 U120.8(VBUS) U120.9(VIN-) ; also on sheet 79
VSYS_MCUIO_1V8_N: R429.1 R575.2 TP203.1(TP)
VSYS_MCUIO_1V8_P: R429.4 R574.2 TP202.1(TP)
VSYS_MCUIO_3V3: R1058.2 ; also on sheet 16 17 18 21 22 23 35 36 43 44 48 49 55 62 65 68
VSYS_MCUIO_3V3_IN+: C387.2 R570.1 U117.10(VIN+) ; also on sheet 79
VSYS_MCUIO_3V3_IN-: C387.1 R571.1 U117.8(VBUS) U117.9(VIN-) ; also on sheet 79
VSYS_MCUIO_3V3_N: R571.2 R1058.1 TP199.1(TP)
VSYS_MCUIO_3V3_P: R570.2 R1058.4 TP198.1(TP)

Not connected (* = marked no-connect by the designer): U32 3(ALERT)*; U56 3(ALERT)*; U60 3(ALERT)*; U65 3(ALERT)*; U83 2(A0) 3(ALERT)*; U94 3(ALERT)*; U100 3(ALERT)*; U106 3(ALERT)*; U115 3(ALERT)*; U117 3(ALERT)*; U118 3(ALERT)*; U120 3(ALERT)*; U128 3(ALERT)*; U172 3(ALERT)*; U184 3(ALERT)*; U189 3(ALERT)*; U193 3(ALERT)*; U195 3(ALERT)*; U199 3(ALERT)*; U203 3(ALERT)*; U208 3(ALERT)*; U209 3(ALERT)*; U212 3(ALERT)*; U215 3(ALERT)*; U218 3(ALERT)*; U221 3(ALERT)*; U224 3(ALERT)*; U226 3(ALERT)*; U229 3(ALERT)*; U232 3(ALERT)*; U236 3(ALERT)*; U239 3(ALERT)*

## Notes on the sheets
sheet 74
- (TI EVM Only)
- SOC Current Sense Resistors
- (TI EVM Only)
- Reserved for future
- Low voltage PHY rail supplied from output side
  of CORE current sense R in order to minimize
  voltage differences btw Core logic & PHY modules.
- EVM default selects VDA_USB_3V3_REG
  (best USB2.0 eye performance)
  Alternative option using VDD_IO_3V3_LS
  (only for No USB/USB Erros Allowed)
- (TI EVM Only)
- (TI EVM Only)
sheet 75
- (TI EVM Only)
- (TI EVM Only)
- EVM development & evaluation test circuitry
- LPDDR4 SDRAM Current Sense Resistors
- Peripheral Current Sense Resistors
- CORE, AVS and DDR input supply sense resistors
- (TI EVM Only)
sheet 76
- Note:  The design supports current/voltage measurements
  using either INA226 or INA231. The EVM will be assembled
   with either INA226 or INA231, but not both
  (implemented via dual or stacked PCB footprint).
  These two INA devices are register compatible
  – so functionality and performance should not be impacted with either INA
- CURRENT MONITORS #1
- I2C ADDRESS: 100-0011 (0x43)
- I2C ADDRESS: 100-0010 (0x42)
- I2C ADDRESS: 100-0000 (0x40)
- Reserved for future
- I2C ADDRESS: 100-0110 (0x46)
- I2C ADDRESS: 100-0100 (0x44)
- I2C ADDRESS: 100-0101 (0x45)
- Reserved for future
- I2C ADDRESS: 100-1101 (0x49)
- I2C ADDRESS: 100-0111 (0x47)
- I2C ADDRESS: 100-1000 (0x48)
- Reserved for future
- I2C ADDRESS: 100-1101 (0x4A)
- I2C ADDRESS: 100-1100 (0x4C)
- I2C ADDRESS: 100-1101 (0x4B)
- I2C ADDRESS: 100-1101 (0x4D)
- I2C ADDRESS: 100-1110 (0x4E)
- I2C ADDRESS: 100-1111(0x4F)
- I2C ADDRESS: 100-1110 (0x41)
sheet 77
- Note:  The design supports current/voltage measurements
  using either INA226 or INA231. The EVM will be assembled
  with either INA226 or INA231, but not both
  (implemented via dual or stacked PCB footprint).
  These two INA devices are register compatible–
  so functionality and performance should not be impacted with either INA
- CURRENT MONITORS #2
- I2C ADDRESS: 100-0001 (0x41)
- I2C ADDRESS: 100-0000 (0x40)
- I2C ADDRESS: 100-0010 (0x42)
- Reserved for future
- I2C ADDRESS: 100-0100 (0x44)
- I2C ADDRESS: 100-0011 (0x43)
- I2C ADDRESS: 100-0101 (0x45)
- I2C ADDRESS: 100-0111 (0x47)
- I2C ADDRESS: 100-1000 (0x48)
- I2C ADDRESS: 100-0110 (0x46)
- I2C ADDRESS: 100-1010 (0x4A)
- I2C ADDRESS: 100-1001 (0x49)
- I2C ADDRESS: 100-1011 (0x4B)
- I2C ADDRESS: 100-1110 (0x4E)
- I2C ADDRESS: 100-1100 (0x4C)
- I2C ADDRESS: 100-1111(0x4F)
- I2C ADDRESS: 100-1101 (0x4D)
